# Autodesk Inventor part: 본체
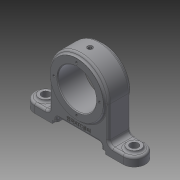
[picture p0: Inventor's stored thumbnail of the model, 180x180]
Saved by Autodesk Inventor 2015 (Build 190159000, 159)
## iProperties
Created: 2019-05
Part Number: 본체
Material: 일반
Document SubType Name: Modeling
Designer: now
Density: 1 g/cm^3
Appearance: 기본값
Author: now
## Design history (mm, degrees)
sketch "스케치1"
  geometry: C1 r 40 at (0, 0); 1 further point
  constraints: 1 centre point, 1 coincident
  dimensions: "d0" = 80 diameter of C1
extrude "돌출1" new body sketch "스케치1" stored distance "d1" = 30; taper "d2" = 0 deg
sketch "스케치2"
  geometry: C1 r 36 at (0, 0); 1 further point
  constraints: 1 centre point, 1 coincident
  dimensions: "d3" = 72 diameter of C1
extrude "돌출2" join sketch "스케치2" distance "d4" = 3; taper "d5" = 0 deg
sketch "스케치3"
  geometry: 1 further point
hole "구멍1" sketch "스케치3" at (0, 0) diameter "d6" = 52; stored, may be unused: countersink angle "d10" = 90 deg, drill point angle "d12" = 118 deg; dims "d7" = 6, "d8" = 4, "d9" = 2, "d11" = 8
node "작업 평면1"
sketch "스케치4"
  geometry: L1 (-75, -15)-(75, -15); L2 (75, -15)-(75, 15); L3 (75, 15)-(-75, 15); L4 (-75, 15)-(-75, -15); 3 further points
  constraints: 8 end point, 2 midpoint, 2 parallel, 1 horizontal, 1 horizontal alignment, 1 perpendicular, 1 vertical alignment
  dimensions: "d14" = 150 distance between parallel lines of L4 L2; "d15" = 30 distance between parallel lines of L3 L1
extrude "돌출3" join sketch "스케치4" distance "d16" = 12; taper "d17" = 0 deg
fillet "모깎기1" dims "d18" = 15
sketch "스케치5"
  geometry: L1 (60, -15)-(-60, -15) reference; L2 (-60, 15)-(60, 15) reference; C1 r 9 at (60, 0); A1 r 15 centre (60, 0) between (60, -15) and (60, 15) reference; A2 r 15 centre (-60, 0) between (-60, 15) and (-60, -15) reference; 1 further point
  constraints: 1 centre point, 1 coincident
  dimensions: "d19" = 18 diameter of C1
extrude "돌출4" join sketch "스케치5" distance "d20" = 3; taper "d21" = 0 deg
sketch "스케치6"
  geometry: C1 r 9 at (0, 0) reference; 1 further point
hole "구멍2" sketch "스케치6" at (0, 0) diameter "d22" = 11; stored, may be unused: countersink angle "d26" = 90 deg, drill point angle "d28" = 118 deg; dims "d23" = 6, "d24" = 4, "d25" = 2, "d27" = 8
sketch "스케치7"
  geometry: L1 (60, -15)-(-60, -15) reference; L2 (-60, 15)-(60, 15) reference; L3 (40, -15)-(-40, -15); L4 (-40, -15)-(-40, 15); L5 (-40, 15)-(40, 15); L6 (40, 15)-(40, -15); L7 (40, -15)-(-40, 15); L8 (-40, -15)-(40, 15); C1 r 5.5 at (-60, 0) reference; C2 r 9 at (-60, 0) reference; C3 r 5.5 at (60, 0) reference; C4 r 9 at (60, 0) reference; A1 r 15 centre (60, 0) between (60, -15) and (60, 15) reference; A2 r 15 centre (-60, 0) between (-60, 15) and (-60, -15) reference; 1 further point
  constraints: 12 end point, 2 midpoint, 2 parallel, 1 horizontal, 1 perpendicular, 1 point on line
  dimensions: "d29" = 40 distance from line of point (0, 0) L4
extrude "돌출5" join sketch "스케치7" stored distance "d30" = 3; taper "d31" = 0 deg
sketch "스케치8"
  geometry: L1 (100, 60)-(100, 12) reference; L2 (100, 12)-(120, 12) reference; L3 (120, 0)-(120, 12) reference; L4 (120, 0)-(0, 0) reference; L5 (0, 0)-(0, 12) reference; L6 (0, 12)-(20, 12) reference; L7 (20, 12)-(20, 60) reference; L8 (24, 0)-(96, 0); L9 (96, 0)-(96, 4); L10 (96, 4)-(24, 4); L11 (24, 4)-(24, 0); C1 r 26 at (60, 60) reference; C2 r 36 at (60, 60) reference; A1 r 40 centre (60, 60) between (100, 60) and (20, 60) reference; 2 further points
  constraints: 8 end point, 2 parallel, 1 horizontal, 1 midpoint, 1 perpendicular, 1 point on line, 1 vertical alignment
  dimensions: "d32" = 4 distance between parallel lines of L4 L10; "d33" = 72 distance between parallel lines of L9 L11
extrude "돌출6" cut sketch "스케치8" stored distance "d34" = 3; taper "d35" = 0 deg
sketch "스케치9"
  geometry: L1 (-20, 60)-(-20, 12) reference; L2 (-20, 12)-(0, 12) reference; L3 (0, 0)-(0, 12) reference; L4 (0, 0)-(-24, 0) reference; L5 (-24, 0)-(-24, 4) reference; L6 (-24, 4)-(-96, 4) reference; L7 (-96, 4)-(-96, 0) reference; L8 (-96, 0)-(-120, 0) reference; L9 (-120, 0)-(-120, 12) reference; L10 (-120, 12)-(-100, 12) reference; L11 (-100, 12)-(-100, 60) reference; L12 (-90, 4)-(-30, 4); L13 (-30, 4)-(-30, 10); L14 (-30, 10)-(-90, 10); L15 (-90, 10)-(-90, 4); C1 r 26 at (-60, 60) reference; C2 r 36 at (-60, 60) reference; A1 r 40 centre (-60, 60) between (-20, 60) and (-100, 60) reference; 2 further points
  constraints: 8 end point, 2 parallel, 1 horizontal, 1 midpoint, 1 perpendicular, 1 point on line, 1 vertical alignment
  dimensions: "d36" = 6 distance between parallel lines of L12 L14; "d37" = 60 distance between parallel lines of L13 L15
extrude "돌출7" cut sketch "스케치9" stored distance "d38" = 3; taper "d39" = 0 deg
sketch "스케치10"
  geometry: 2 further points
  constraints: 1 vertical alignment
  dimensions: "d40" = 31 distance of point (0, 0) point (0, 31)
hole "구멍3" sketch "스케치10" at (0, 31) diameter "d41" = 3.242; stored, may be unused: countersink angle "d45" = 90 deg, drill point angle "d47" = 118 deg; dims "d42" = 6, "d43" = 4, "d44" = 2, "d46" = 8
node "작업 평면2"
sketch "스케치11"
  geometry: 1 further point
hole "구멍4" sketch "스케치11" at (0, 0) diameter "d52" = 4.917; stored, may be unused: countersink angle "d56" = 90 deg, drill point angle "d58" = 118 deg; dims "d53" = 8, "d54" = 7, "d55" = 1, "d57" = 10
sketch "스케치12"
  geometry: C1 r 1 at (0, 0); 1 further point
  constraints: 1 centre point, 1 coincident
  dimensions: "d59" = 2 diameter of C1
extrude "돌출8" cut sketch "스케치12" distance "d60" = 40; taper "d61" = 0 deg
sketch "스케치13"
  geometry: L1 (-20, 60)-(-20, 12) reference; L2 (-20, 12)-(0, 12) reference; L3 (0, 0)-(0, 12) reference; L4 (0, 0)-(-24, 0) reference; L5 (-24, 0)-(-24, 4) reference; L6 (-24, 4)-(-30, 4) reference; L7 (-30, 4)-(-30, 10) reference; L8 (-30, 10)-(-90, 10) reference; L9 (-90, 10)-(-90, 4) reference; L10 (-90, 4)-(-96, 4) reference; L11 (-96, 4)-(-96, 0) reference; L12 (-96, 0)-(-120, 0) reference; L13 (-120, 0)-(-120, 12) reference; L14 (-120, 12)-(-100, 12) reference; L15 (-100, 12)-(-100, 60) reference; C1 r 1.621 at (-29, 60) reference; C2 r 1.621 at (-60, 29) reference; C3 r 1.621 at (-91, 60) reference; C4 r 1.621 at (-60, 91) reference; C5 r 26 at (-60, 60) reference; C6 r 36 at (-60, 60) reference; A1 r 40 centre (-60, 60) between (-20, 60) and (-100, 60) reference; 2 further points
  constraints: 1 vertical alignment, 1 other
  dimensions: "d62" = 7 distance from line of L8 point (-60, 17)
feature "엠보싱1" sketch "스케치13" dims "d63" = 0.5, "d64" = 0
fillet "모깎기2" dims "d65" = 6
fillet "모깎기3" dims "d66" = 3
fillet "모깎기4" dims "d67" = 3
fillet "모깎기5" dims "d68" = 3
fillet "모깎기6" dims "d69" = 3
chamfer "모따기1" distance "d70" = 1; stored, may be unused: second distance "d71" = 2, angle "d72" = 45 deg
sketch "스케치14"
  geometry: C1 r 1.5 at (0, 26); 3 further points
  constraints: 3 vertical alignment, 1 centre point, 2 other
  dimensions: "d73" = 3 diameter of C1
extrude "돌출9" cut sketch "스케치14" stored distance "d74" = 40; taper "d75" = 0 deg
node "솔리드1"
mirror "대칭1"
mirror "대칭2"
pattern_circular "원형 패턴1" dims angle "d49" = 360 deg
mirror "대칭3"
node "절단 모서리 투영1"
node "절단 모서리 투영2"
node "절단 모서리 투영3"
node "절단 모서리 투영4"
node "절단 모서리 투영5"
node "절단 모서리 투영6"
